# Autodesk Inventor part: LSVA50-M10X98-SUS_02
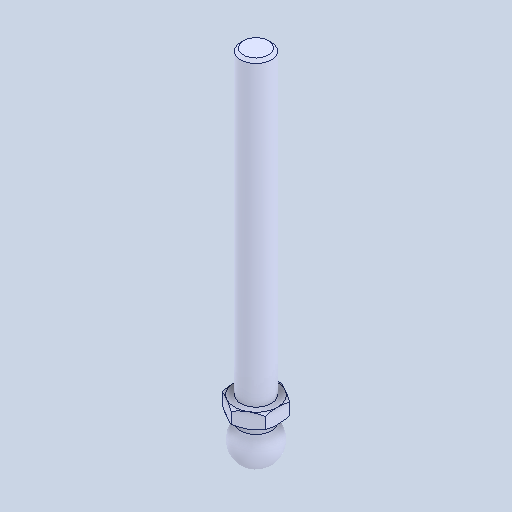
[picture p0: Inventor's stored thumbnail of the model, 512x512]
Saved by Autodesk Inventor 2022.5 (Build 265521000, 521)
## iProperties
Created: 2024-08
Part Number: LSVA50-M10X98-SUS_02
Material: 一般
Document SubType Name: Modeling
Designer: ImaoCorp
Density: 1 g/cm^3
Appearance: 既定
Author: ImaoCorp
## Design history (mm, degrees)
feature "LSVA50-M10X98-SUS_02"
node "ソリッド1"
